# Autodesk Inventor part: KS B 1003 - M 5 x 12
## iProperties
IsCustomPart: 0
Created: 2009-02
Part Number: KS B 1003 - M 5 x 12
Material: 강, 연강
Description: 6각머리 태핑 나사
Document SubType Name: Modeling
Standard: KS B 1003
Designer: KYOUNG IL JANG
Standards Organization: KS
Language: ko-KR
Size Designation: M 5 x 12
Categories: <MemberInstance><Categories><Category DisplayName="조임쇠" InternalName="e4da775c-781d-43d5-af7c-5136215cf5a6" Mnemonic="FSTN"><Category DisplayName="볼트" InternalN
Density: 7.86 g/cm^3
Mass: 3.72825 g
Surface Area: 4.62574 cm^2
Volume: 0.474332 cm^3
Author: KYOUNG IL JANG
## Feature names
1. Fillet2
